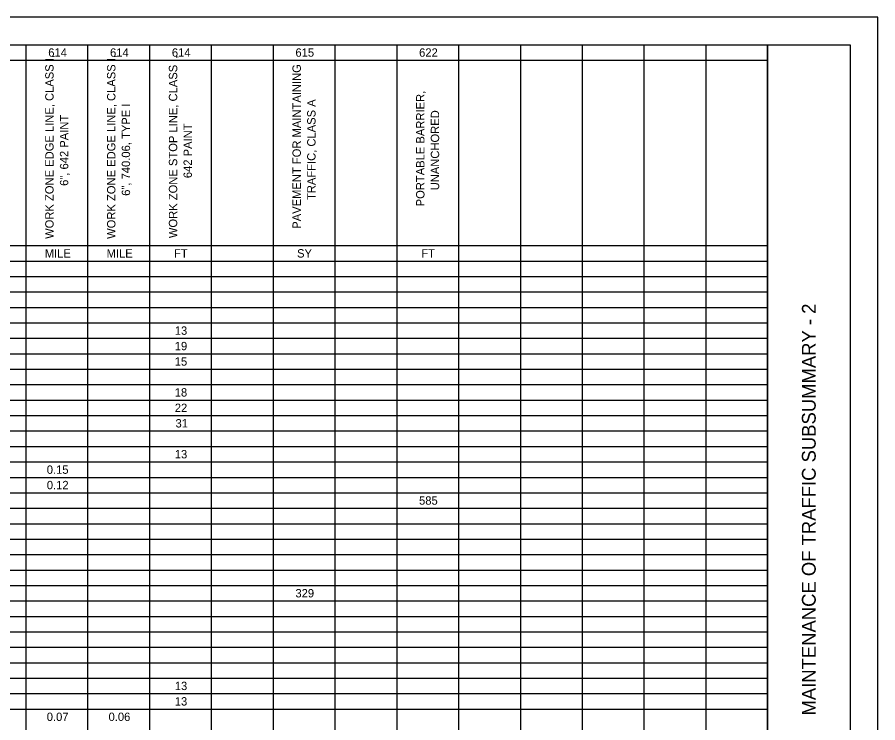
# Model space of a CAD drawing. Extents: x -0.1 to 36.1, y 0 to 22.
# Drawn here: x 18.28 to 33.88, y 9.19 to 21.98 of the extents above; entities that cross this region are included whole.
import ezdxf

# ---------------------------------------------------------------- set-up
doc = ezdxf.new("R2010")
doc.units = 0
for name, color, linetype in [('Default', 7, 'Continuous'), ('SH_Border', 7, 'Continuous'), ('SH_Cut_Line', 7, 'Continuous'), ('SH_Data', 7, 'Continuous')]:
    doc.layers.add(name, color=color, linetype=linetype)

msp = doc.modelspace()

# ---------------------------------------------------------------- linework, layer by layer
at = {"layer": 'Default'}
for p, q in [((1.376, 21.475), (31.879, 21.475)), ((18.439, 21.475), (18.439, 0.475)), ((19.559, 21.475), (19.559, 0.475)), ((20.679, 21.475), (20.679, 0.475)), ((21.799, 21.475), (21.799, 0.475)), ((22.919, 21.475), (22.919, 0.475)), ((24.039, 21.475), (24.039, 0.475)), ((25.159, 21.475), (25.159, 0.475)), ((26.279, 21.475), (26.279, 0.475)), ((27.399, 21.475), (27.399, 0.475)), ((28.519, 21.475), (28.519, 0.475)), ((29.639, 21.475), (29.639, 0.475)), ((30.759, 21.475), (30.759, 0.475)), ((31.879, 21.475), (31.879, 0.475)), ((8.359, 21.195), (31.879, 21.195)), ((8.359, 17.835), (31.879, 17.835)), ((1.376, 17.555), (31.879, 17.555)), ((1.376, 17.275), (31.879, 17.275)), ((1.376, 16.995), (31.879, 16.995)), ((1.376, 16.715), (31.879, 16.715)), ((1.376, 16.435), (31.879, 16.435)), ((1.376, 16.155), (31.879, 16.155)), ((1.376, 15.875), (31.879, 15.875)), ((1.376, 15.595), (31.879, 15.595)), ((1.376, 15.315), (31.879, 15.315)), ((1.376, 15.035), (31.879, 15.035)), ((1.376, 14.755), (31.879, 14.755)), ((1.376, 14.475), (31.879, 14.475)), ((1.376, 14.195), (31.879, 14.195)), ((1.376, 13.915), (31.879, 13.915)), ((1.376, 13.635), (31.879, 13.635)), ((1.376, 13.355), (31.879, 13.355)), ((1.376, 13.075), (31.879, 13.075)), ((1.376, 12.795), (31.879, 12.795)), ((1.376, 12.515), (31.879, 12.515)), ((1.376, 12.235), (31.879, 12.235)), ((1.376, 11.955), (31.879, 11.955)), ((1.376, 11.675), (31.879, 11.675)), ((1.376, 11.395), (31.879, 11.395)), ((1.376, 11.115), (31.879, 11.115)), ((1.376, 10.835), (31.879, 10.835)), ((1.376, 10.555), (31.879, 10.555)), ((1.376, 10.275), (31.879, 10.275)), ((1.376, 9.995), (31.879, 9.995)), ((1.376, 9.715), (31.879, 9.715)), ((1.376, 9.435), (31.879, 9.435))]:
    msp.add_line(p, q, dxfattribs=at)
at = {"layer": 'SH_Border'}
msp.add_line((31.876, 0.475), (31.876, 21.475), dxfattribs=at)
msp.add_lwpolyline([(1.376, 21.475), (33.376, 21.475), (33.376, 0.475), (1.376, 0.475)], close=True, dxfattribs=at)
at = {"layer": 'SH_Cut_Line'}
msp.add_lwpolyline([(-0.124, -0.025), (33.876, -0.025), (33.876, 21.975), (-0.124, 21.975)], close=True, dxfattribs=at)

# ---------------------------------------------------------------- texts
at = {"layer": 'Default'}
for s, p in [('614', (18.845, 21.259)), ('614', (19.965, 21.259)), ('614', (21.085, 21.259)), ('615', (23.324, 21.259)), ('622', (25.565, 21.259)), ('MILE', (18.782, 17.619)), ('MILE', (19.902, 17.619)), ('FT', (21.125, 17.619)), ('SY', (23.353, 17.619)), ('FT', (25.605, 17.619)), ('13', (21.138, 16.219)), ('19', (21.137, 15.939)), ('15', (21.137, 15.659)), ('18', (21.137, 15.099)), ('22', (21.138, 14.819)), ('31', (21.151, 14.539)), ('13', (21.138, 13.979)), ('0.15', (18.818, 13.699)), ('0.12', (18.819, 13.419)), ('585', (25.564, 13.139)), ('329', (23.324, 11.459)), ('13', (21.138, 9.779)), ('13', (21.138, 9.499)), ('0.07', (18.818, 9.219)), ('0.06', (19.938, 9.219))]:
    msp.add_text(s, height=0.1515, dxfattribs=at).set_placement(p)
for s, height, p in [('WORK ZONE EDGE LINE, CLASS I, ', 0.15153, (18.942, 17.957)), ('WORK ZONE EDGE LINE, CLASS I, ', 0.15153, (20.062, 17.957)), ('WORK ZONE STOP LINE, CLASS I, ', 0.15153, (21.182, 17.971)), ('PAVEMENT FOR MAINTAINING ', 0.15153, (23.422, 18.141)), ('PORTABLE BARRIER, ', 0.15153, (25.662, 18.547)), ('TRAFFIC, CLASS A', 0.15153, (23.688, 18.662)), ('6", 740.06, TYPE I', 0.15153, (20.328, 18.738)), ('UNANCHORED', 0.1515, (25.928, 18.837)), ('6", 642 PAINT', 0.15153, (19.208, 18.918)), ('642 PAINT', 0.1515, (21.448, 19.058))]:
    msp.add_text(s, height=height, rotation=90, dxfattribs=at).set_placement(p)
at = {"layer": 'SH_Data'}
msp.add_text('MAINTENANCE OF TRAFFIC SUBSUMMARY - 2', height=0.25, rotation=90, dxfattribs=at).set_placement((32.751, 9.318))

doc.saveas('drawing.dxf')
